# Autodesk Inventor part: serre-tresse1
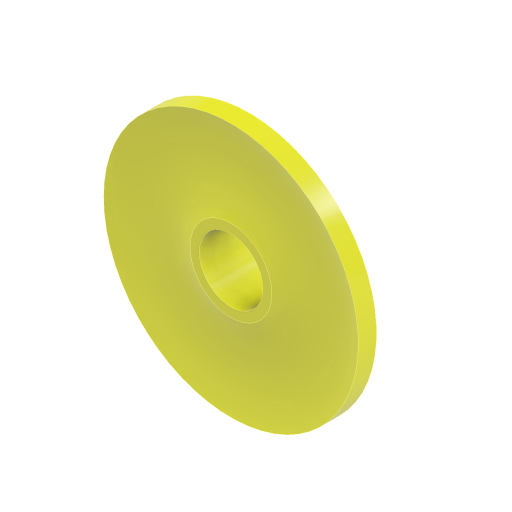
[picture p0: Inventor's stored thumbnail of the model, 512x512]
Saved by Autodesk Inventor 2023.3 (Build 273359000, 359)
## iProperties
Created: 2024-11
Part Number: serre-tresse1
Material: Générique
Description: STEP AP203
Document SubType Name: Modeling
Designer: Thier
Density: 1 g/cm^3
Appearance: Jaune
Sending System: SolidWorks 2017
Preprocessor: SwSTEP 2.0
Title: serre-tresse1.STEP
Revision Number: ANY
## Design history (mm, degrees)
feature "Enlever de la matière-Balayage11"
node "Solide1"
